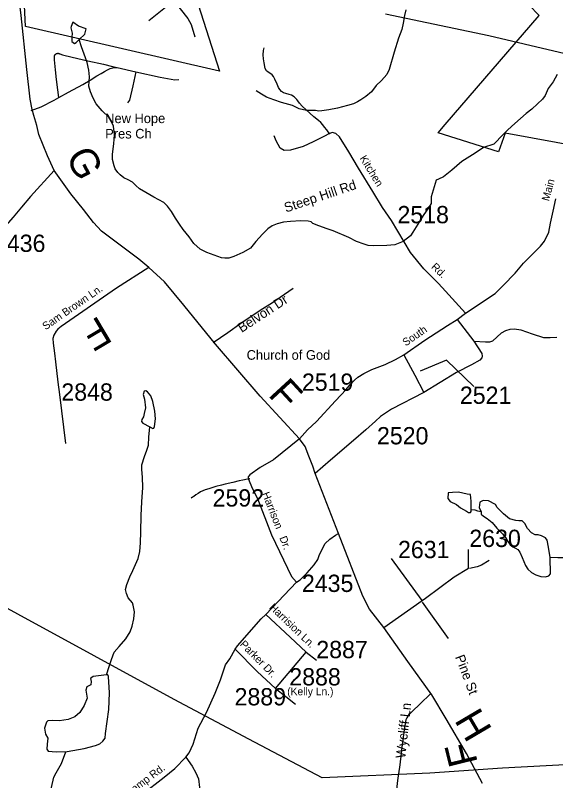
# Model space of a CAD drawing. Extents: x 1268485 to 1426702, y 514839 to 616766.
# Drawn here: x 1377903 to 1382514, y 533756 to 540290 of the extents above; entities that cross this region are included whole.
import ezdxf

# ---------------------------------------------------------------- set-up
doc = ezdxf.new("R2010")
doc.units = 0
for name, color, linetype in [('Old_Level_10', 7, 'Continuous'), ('Old_Level_11', 7, 'Continuous'), ('Old_Level_22', 7, 'Continuous'), ('Old_Level_29', 7, 'Continuous'), ('Old_Level_32', 7, 'Continuous'), ('Old_Level_35', 7, 'Continuous'), ('Old_Level_48', 7, 'Continuous'), ('Old_Level_49', 7, 'Continuous'), ('Old_Level_56', 7, 'Continuous'), ('Old_Level_62', 7, 'Continuous'), ('Old_Level_8', 7, 'Continuous')]:
    doc.layers.add(name, color=color, linetype=linetype)

msp = doc.modelspace()

# ---------------------------------------------------------------- linework, layer by layer
at = {"layer": 'Old_Level_11'}
msp.add_lwpolyline([(1381816.1, 537121.031), (1381582.771, 537345.868), (1381358.085, 537250.745)], dxfattribs=at)
at = {"layer": 'Old_Level_22'}
msp.add_line((1378670.085, 539451.621), (1378670.085, 539451.621), dxfattribs=at)
at = {"layer": 'Old_Level_29'}
msp.add_line((1380661.798, 535865.812), (1380461.639, 536377.474), dxfattribs=at)
for points in [[(1378235.034, 538965.895), (1378176.071, 539089.297), (1378102.134, 539273.422), (1378086.167, 539347.983), (1378059.556, 539433.197), (1378047.317, 539485.38), (1378028.688, 539573.256), (1378002.076, 539826.232), (1377953.11, 540287.991), (1377902.548, 540705.537), (1377889.243, 540875.964), (1377870.614, 541040.532), (1377838.68, 541160.363), (1377796.102, 541258.891), (1377745.541, 541328.126), (1377734.896, 541352.093), (1377657.723, 541437.306), (1377290.855, 541774.023), (1377172.929, 541894.415), (1377036.385, 542002.767)], [(1379043.439, 538138.202), (1378956.548, 538207.427), (1378832.888, 538301.982), (1378638.46, 538448.211), (1378570.188, 538520.446), (1378484.277, 538632.183), (1378377.785, 538767.249), (1378235.034, 538965.895)], [(1380328.199, 536675.443), (1379993.044, 537039.628), (1379609.789, 537482.067), (1379341.354, 537816.154), (1379176.88, 538014.8), (1379043.439, 538138.202)], [(1380461.639, 536377.474), (1380441.468, 536440.679), (1380408.86, 536525.906), (1380376.299, 536609.227), (1380328.199, 536675.443)], [(1381047.378, 535063.728), (1380925.576, 535220.991), (1380868.165, 535332.354), (1380661.798, 535865.812)], [(1381889.32, 533731.881), (1381754.307, 533989.571), (1381580.368, 534284.94), (1381457.788, 534488.101), (1381251.351, 534773.539), (1381047.378, 535063.728)]]:
    msp.add_lwpolyline(points, dxfattribs=at)
at = {"layer": 'Old_Level_32'}
for p, q in [((1381672.694, 537694.257), (1381744.069, 537748.434)), ((1381672.694, 537694.257), (1381816.221, 537507.648)), ((1381374, 535293.225), (1381112.548, 535652.145)), ((1380041.048, 535175.725), (1380302.593, 535451.964)), ((1381047.378, 535063.728), (1381374, 535293.225)), ((1380124.155, 534543.006), (1380383.809, 534852.45)), ((1380383.809, 534852.45), (1380472.498, 534785.296))]:
    msp.add_line(p, q, dxfattribs=at)
for points in [[(1380606.717, 539289.444), (1380572.581, 539275.9), (1380546.203, 539262.356), (1380445.346, 539209.684), (1380358.455, 539169.052), (1380250.751, 539139.737), (1380197.529, 539137.074), (1380162.934, 539155.714), (1380128.338, 539216.962), (1380112.372, 539262.231)], [(1381744.069, 537748.434), (1381573.881, 537934.445), (1381515.336, 538001.018), (1381387.601, 538124.578), (1381275.833, 538265.714), (1381112.922, 538538.279), (1381037.299, 538648.361), (1380953.51, 538786.811), (1380830.016, 538986.38), (1380749.468, 539125.411), (1380668.783, 539251.822), (1380637.749, 539281.92), (1380606.717, 539289.444)], [(1378235.034, 538965.895), (1378031.882, 538744.026), (1377954.708, 538650.824), (1377885.519, 538565.611), (1377656.128, 538309.97), (1377420.88, 538059.134), (1377223.955, 537846.1), (1377202.666, 537811.482), (1377108.533, 537607.766), (1377086.81, 537499.414), (1377058.881, 537087.07), (1377056.303, 536596.66), (1377050.981, 536442.212), (1376998.366, 536149.516), (1376973.54, 536026.113), (1376874.235, 535640.859), (1376787.343, 535300.751), (1376751.286, 535157.206), (1376653.902, 534769.521), (1376618.214, 534698.79), (1376575.545, 534625.801), (1376519.685, 534541.527), (1376487.101, 534485.846)], [(1381744.069, 537748.434), (1381996.987, 537913.971), (1382066.193, 537982.378), (1382167.317, 538088.895), (1382238.265, 538174.32), (1382385.671, 538318.79), (1382417.479, 538362.433), (1382454.718, 538437.678), (1382470.235, 538514.428), (1382493.509, 538618.265), (1382514.456, 538722.103)], [(1379043.439, 538138.202), (1378767.239, 537961.416), (1378292.766, 537632.396), (1378264.321, 537610.959), (1378250.542, 537592.716), (1378230.371, 537559.609), (1378224.164, 537529.51), (1378225.715, 537490.383), (1378236.577, 537404.603), (1378244.336, 537330.863), (1378266.835, 537158.551), (1378279.248, 537051.703), (1378331.228, 536634.092)], [(1381218.838, 537392.167), (1381398.246, 537515.564), (1381590.457, 537641.586), (1381672.694, 537694.257)], [(1381816.221, 537507.648), (1381913.974, 537501.629), (1381951.213, 537501.629), (1381977.591, 537510.658), (1382013.279, 537542.261), (1382052.07, 537578.378), (1382087.758, 537599.447), (1382126.549, 537611.486), (1382163.788, 537612.991), (1382216.544, 537603.961), (1382314.297, 537569.349), (1382409.723, 537539.251), (1382468.258, 537540.469), (1382524.147, 537543.132)], [(1381816.221, 537507.648), (1381882.941, 537403.813), (1381887.596, 537379.734), (1381884.493, 537366.19), (1381865.873, 537345.122), (1381796.05, 537307.5), (1381667.263, 537239.779), (1381388.745, 537071.232)], [(1380328.199, 536675.443), (1380394.919, 536750.688), (1380472.501, 536822.923), (1380633.871, 536997.491), (1380726.97, 537096.814), (1380767.313, 537144.97), (1380798.345, 537175.069), (1380826.275, 537202.157), (1380876.661, 537231.429), (1380944.2, 537265.362), (1381058.246, 537309.005), (1381148.24, 537351.143), (1381218.838, 537392.167)], [(1381218.838, 537392.167), (1381311.163, 537218.712), (1381388.745, 537071.232)], [(1381388.745, 537071.232), (1381113.503, 536928.654), (1381020.363, 536864.743), (1380975.123, 536824.799), (1380892.628, 536750.237), (1380788.843, 536659.697), (1380593.529, 536493.35), (1380461.639, 536377.474)], [(1380328.199, 536675.443), (1380104.915, 536494.397), (1379991.492, 536428.64), (1379904.802, 536366.581), (1379888.836, 536350.603), (1379892.187, 536329.317), (1379922.953, 536253.755), (1379968.217, 536163.779), (1380088.622, 535856.236), (1380259.147, 535498.616), (1380302.593, 535451.964)], [(1380302.593, 535451.964), (1380333.626, 535471.528), (1380392.588, 535531.724), (1380453.1, 535599.474), (1380484.133, 535644.621), (1380497.324, 535686.729), (1380546.976, 535780.033), (1380585.765, 535818.438), (1380633.867, 535853.05), (1380661.798, 535865.812)], [(1381374, 535293.225), (1381404.256, 535313.542), (1381647.865, 535495.635), (1381768.895, 535570.881), (1381769.517, 535730.481)], [(1379780.255, 534877.478), (1379798.31, 534907.191), (1380001.13, 535138.444), (1380041.048, 535175.725)], [(1380041.048, 535175.725), (1380248.091, 534982.401), (1380383.809, 534852.45)], [(1379357.644, 533956.097), (1379385.573, 533995.225), (1379421.262, 534067.46), (1379462.379, 534204.405), (1379535.43, 534339.57), (1379607.281, 534502.008), (1379652.52, 534616.513), (1379697.759, 534744.333), (1379732.354, 534797.591), (1379780.255, 534877.478)], [(1379780.255, 534877.478), (1379967.439, 534687.477), (1380124.155, 534543.006)], [(1380124.155, 534543.006), (1380211.823, 534475.287), (1380294.059, 534410.576)], [(1378230.88, 532361.466), (1378262.2, 532445.754), (1378378.559, 532747.667), (1378510.449, 533125.395), (1378547.688, 533241.272), (1378570.963, 533295.449), (1378606.65, 533333.071), (1378698.197, 533421.86), (1378869.654, 533552.787), (1378981.372, 533637.061), (1379172.224, 533786.046), (1379263.771, 533859.785), (1379357.644, 533956.097)], [(1379357.644, 533956.097), (1379411.951, 533880.853), (1379442.985, 533822.162), (1379464.707, 533772.5), (1379474.017, 533697.255), (1379467.811, 533632.545), (1379449.967, 533581.378), (1379437.554, 533537.736)]]:
    msp.add_lwpolyline(points, dxfattribs=at)
at = {"layer": 'Old_Level_35'}
for p, q in [((1379254.542, 540414.048), (1379041.083, 540243.445)), ((1378771.747, 539843.338), (1378930.047, 539808.017)), ((1381373.345, 535279.852), (1381597.262, 534970.428))]:
    msp.add_line(p, q, dxfattribs=at)
for points in [[(1379254.542, 540414.048), (1379374.702, 540262.823), (1379403.717, 540212.38), (1379434.783, 540105.753)], [(1378236.458, 539932.996), (1378236.458, 539933.663), (1378236.356, 539934.381), (1378236.356, 539935.047), (1378236.356, 539935.714), (1378236.356, 539936.38), (1378236.356, 539937.046), (1378236.356, 539937.764), (1378236.458, 539938.43), (1378236.458, 539939.148), (1378236.663, 539939.815), (1378236.766, 539940.481), (1378236.868, 539941.147), (1378236.971, 539941.813), (1378237.176, 539942.48), (1378237.278, 539943.146), (1378237.381, 539943.813), (1378237.586, 539944.428), (1378237.894, 539945.146), (1378237.996, 539945.761), (1378238.201, 539946.376), (1378238.509, 539947.042), (1378238.714, 539947.709), (1378239.021, 539948.324), (1378239.329, 539948.939), (1378239.637, 539949.503), (1378240.047, 539950.118), (1378240.252, 539950.682), (1378240.662, 539951.298), (1378240.969, 539951.861), (1378241.38, 539952.425), (1378241.79, 539952.989), (1378242.097, 539953.553), (1378242.61, 539954.117), (1378243.02, 539954.629), (1378243.328, 539955.194), (1378243.84, 539955.706), (1378244.353, 539956.167), (1378244.763, 539956.68), (1378245.275, 539957.192), (1378245.788, 539957.603), (1378246.301, 539958.064), (1378246.711, 539958.577), (1378247.326, 539958.987), (1378247.839, 539959.397), (1378248.351, 539959.807), (1378248.966, 539960.166), (1378249.479, 539960.576), (1378250.094, 539960.935), (1378250.607, 539961.293), (1378251.222, 539961.704), (1378251.837, 539962.011), (1378252.452, 539962.319), (1378253.17, 539962.626), (1378253.785, 539962.934), (1378254.4, 539963.191), (1378255.015, 539963.446), (1378255.631, 539963.703), (1378256.246, 539963.959), (1378256.861, 539964.113), (1378257.476, 539964.318), (1378258.091, 539964.523), (1378258.911, 539964.677), (1378259.527, 539964.882), (1378260.142, 539964.984), (1378260.859, 539965.139), (1378261.475, 539965.241), (1378262.295, 539965.292), (1378262.91, 539965.394), (1378263.525, 539965.446), (1378264.243, 539965.497), (1378264.858, 539965.549), (1378265.576, 539965.549), (1378266.293, 539965.549), (1378267.011, 539965.549), (1378267.626, 539965.497), (1378268.344, 539965.446), (1378268.959, 539965.394), (1378269.677, 539965.292), (1378270.394, 539965.241), (1378271.01, 539965.139), (1378271.727, 539964.984), (1378272.342, 539964.882), (1378272.958, 539964.677), (1378273.675, 539964.523), (1378274.393, 539964.318), (1378275.008, 539964.113), (1378275.623, 539963.959), (1378276.238, 539963.703), (1378276.854, 539963.446), (1378277.469, 539963.191), (1378278.084, 539962.934), (1378278.802, 539962.626), (1378279.417, 539962.319), (1378280.032, 539962.011), (1378280.647, 539961.704), (1378281.16, 539961.293), (1378281.775, 539960.935), (1378282.39, 539960.576), (1378282.903, 539960.166)], [(1378282.903, 539960.166), (1378304.125, 539951.143), (1378387.787, 539932.996), (1378522.711, 539901.726), (1378655.79, 539871.481), (1378733.402, 539853.385), (1378771.747, 539843.338)], [(1380586.253, 539276.061), (1380560.519, 539312.048), (1380541.961, 539335.269), (1380526.275, 539355.365), (1380509.05, 539375.101), (1380490.596, 539390.993), (1380450.713, 539424.416), (1380352.083, 539514.485), (1380328.707, 539540.322), (1380313.328, 539560.827), (1380305.126, 539572.054), (1380281.033, 539594.199), (1380260.22, 539607.323), (1380240.022, 539613.679), (1380210.29, 539621.676), (1380191.63, 539627.828), (1380173.483, 539639.259), (1380159.642, 539655.663), (1380150.004, 539672.58), (1380136.266, 539701.185), (1380118.016, 539744.451), (1380106.738, 539767.519), (1380095.153, 539781.77), (1380074.853, 539795.509), (1380059.166, 539804.634), (1380047.376, 539817.039), (1380034.355, 539835.751), (1380025.333, 539885.066), (1380020.206, 539918.079), (1380017.336, 539952.066), (1380020.206, 539988.565), (1380027.588, 540011.941)], [(1378272.855, 539587.33), (1378264.755, 539652.793), (1378254.605, 539740.504), (1378244.66, 539824.114), (1378236.458, 539908.8), (1378236.458, 539932.996)], [(1378272.855, 539587.33), (1378356.516, 539632.647), (1378478.42, 539699.186), (1378540.858, 539735.429), (1378598.375, 539771.774), (1378634.669, 539791.87), (1378663.889, 539808.991), (1378688.085, 539824.114), (1378712.282, 539835.238), (1378735.35, 539842.312), (1378752.574, 539844.311), (1378771.747, 539843.338)], [(1378930.047, 539808.017), (1378904.723, 539688.062), (1378876.528, 539566.107), (1378861.354, 539541.962)], [(1378930.047, 539808.017), (1379139.61, 539762.7), (1379264.589, 539738.504), (1379297.91, 539740.504)], [(1378038.378, 539476.499), (1378122.654, 539509.666), (1378235.536, 539566.107), (1378272.855, 539587.33)], [(1379590.725, 537497.49), (1379716.729, 537581.869), (1379828.483, 537661.994), (1379999.906, 537777.694), (1380089.719, 537832.289), (1380272.728, 537961.113)], [(1379904.762, 536332.487), (1379882.924, 536328.95), (1379845.707, 536322.439), (1379812.796, 536314.75), (1379758.355, 536302.396), (1379694.584, 536287.017), (1379662.801, 536279.943), (1379613.793, 536266.922), (1379587.239, 536259.898), (1379553.508, 536248.62), (1379523.468, 536238.625), (1379502.757, 536230.935), (1379484.508, 536222.066), (1379462.67, 536208.482), (1379441.959, 536194.948), (1379424.838, 536182.543), (1379414.277, 536175.417), (1379404.537, 536167.42)], [(1381947.286, 535634.541), (1381881.464, 535596.606), (1381843.222, 535582.048), (1381777.708, 535567.797)], [(1381446.036, 534496.605), (1381357.453, 534410.893), (1381289.479, 534345.994), (1381271.332, 534331.025), (1381259.541, 534320.106), (1381251.339, 534307.854), (1381244.162, 534293.398), (1381235.55, 534274.328), (1381224.58, 534209.89), (1381204.075, 534065.585), (1381183.774, 533892.675), (1381165.627, 533756.982), (1381147.48, 533602.68), (1381140.201, 533553.262), (1381132.511, 533526.913), (1381123.489, 533513.175), (1381110.878, 533495.181), (1381091.398, 533472.677), (1381072.636, 533444.79), (1381056.232, 533420.747), (1381045.467, 533409.674), (1381029.78, 533401.421), (1381000.355, 533393.937)]]:
    msp.add_lwpolyline(points, dxfattribs=at)
at = {"layer": 'Old_Level_48'}
for points in [[(1379461.962, 540383.078), (1379644.124, 539813.886), (1377990.859, 540195.19), (1377979.819, 540374.789)], [(1382752.667, 539161.552), (1382084.001, 539283.376), (1382027.535, 539123.549), (1381510.576, 539286.426), (1381570.067, 539359.063), (1382371.931, 540286.961), (1382283.739, 540378.779)]]:
    msp.add_lwpolyline(points, dxfattribs=at)
at = {"layer": 'Old_Level_49'}
for points in [[(1379461.962, 540383.078), (1379644.124, 539813.886), (1377990.859, 540195.19), (1377979.819, 540374.789)], [(1382752.667, 539161.552), (1382084.001, 539283.376), (1382027.535, 539123.549), (1381510.576, 539286.426), (1381570.067, 539359.063), (1382371.931, 540286.961), (1382283.739, 540378.779)]]:
    msp.add_lwpolyline(points, dxfattribs=at)
at = {"layer": 'Old_Level_56'}
for points in [[(1381061.503, 540301.744), (1381944.122, 540117.691), (1382895.855, 539893.836), (1383489.307, 539753.631), (1384243.94, 539479.72), (1384403.305, 539444.497), (1385295.195, 539229.852), (1386225.65, 539032.439)], [(1386319.571, 534122.074), (1385381.998, 534065.509), (1384514.51, 534011.536), (1383073.945, 533917.273), (1382060.172, 533862.442), (1381439.057, 533821.319), (1380521.804, 533780.153), (1379894.345, 534109.329), (1379257.086, 534448.709), (1377238.959, 535551.224), (1376368.712, 536035.56), (1375939.406, 536278.51), (1373794.637, 537441.607), (1372983.341, 537882.537), (1372761.263, 538001.427), (1371303.275, 538781.963), (1370885.605, 538996.668), (1370094.313, 539437.396), (1369288.815, 539868.206), (1368639.834, 540221.831)]]:
    msp.add_lwpolyline(points, dxfattribs=at)
at = {"layer": 'Old_Level_62'}
for points in [[(1381236.37, 540336.898), (1381223.247, 540288.762), (1381211.867, 540223.299), (1381200.691, 540167.73), (1381173.214, 540093.604), (1381136.817, 539976.211), (1381093.654, 539827.702), (1381072.841, 539785.461), (1381027.73, 539734.66), (1380982.823, 539689.599), (1380941.608, 539636.286), (1380894.753, 539597.839), (1380852.103, 539568.311), (1380821.857, 539550.882), (1380787.409, 539533.555), (1380737.068, 539518.945), (1380652.587, 539496.03), (1380578.256, 539483.574), (1380518.073, 539473.321), (1380493.979, 539471.321), (1380464.042, 539476.038), (1380388.07, 539477.576), (1380324.401, 539491.161), (1380266.884, 539518.586), (1380173.278, 539544.269), (1380107.866, 539567.748), (1380046.248, 539591.124), (1380004.827, 539615.73), (1379959.306, 539644.59)], [(1378447.662, 540082.838), (1378496.772, 540129.436), (1378506.852, 540175.356), (1378442.689, 540196.758), (1378392.783, 540232.428), (1378379.995, 540194.182), (1378377.739, 540181.879), (1378386.864, 540137.382), (1378386.146, 540102.113), (1378385.326, 540067.665), (1378397.117, 540057.617), (1378408.907, 540049.158), (1378423.158, 540058.693), (1378447.662, 540082.838)], [(1378700.081, 539421.289), (1378645.23, 539475.73), (1378592.326, 539533.401), (1378567.412, 539583.947), (1378544.446, 539636.133), (1378531.426, 539684.781), (1378532.246, 539724.151), (1378535.117, 539764.341), (1378530.298, 539822.678), (1378515.637, 539886.962), (1378489.185, 539957.295), (1378468.372, 540020.041), (1378447.662, 540082.838)], [(1382525.43, 539783.308), (1382492.212, 539722.408), (1382448.946, 539665.045), (1382425.775, 539605.58), (1382400.964, 539574.104), (1382360.158, 539534.683), (1382309.203, 539489.776), (1382262.451, 539451.329), (1382164.641, 539367.155), (1382105.483, 539312.509), (1382064.678, 539273.139), (1381985.023, 539190.287), (1381899.471, 539161.749), (1381828.178, 539111.809), (1381714.109, 539040.466), (1381628.558, 538969.124), (1381557.264, 538912.048), (1381514.489, 538890.646), (1381493.101, 538883.512), (1381450.325, 538740.825), (1381450.325, 538683.751), (1381427.376, 538647.525), (1381381.957, 538581.14), (1381338.384, 538507.372), (1381294.913, 538438.474), (1381274.305, 538406.896), (1381213.199, 538358.043), (1381142.559, 538331.591), (1381074.482, 538324.773), (1380958.32, 538321.339), (1380914.336, 538324.67), (1380878.554, 538335.23), (1380813.143, 538360.349), (1380749.679, 538392.03), (1380614.755, 538450.521), (1380565.235, 538467.951), (1380493.672, 538493.172), (1380442.101, 538512.242), (1380426.312, 538526.544), (1380400.475, 538532.798), (1380338.447, 538536.489), (1380252.325, 538530.03), (1380190.195, 538523.878), (1380137.906, 538511.012), (1380093.41, 538491.378), (1380056.911, 538468.309), (1380011.902, 538420.789), (1379956.538, 538357.94), (1379909.376, 538303.089), (1379844.579, 538264.18), (1379767.992, 538232.038), (1379723.598, 538217.377), (1379691.508, 538215.532), (1379661.57, 538218.607), (1379536.488, 538264.59), (1379481.124, 538294.477), (1379426.068, 538341.536), (1379385.16, 538398.131), (1379334.512, 538461.543), (1379303.447, 538508.089), (1379268.485, 538558.84), (1379235.575, 538613.691), (1379202.459, 538660.29), (1379169.138, 538692.995), (1379127.615, 538715.961), (1379086.092, 538738.158), (1379016.784, 538778.092), (1378961.522, 538808.747), (1378931.995, 538835.609), (1378902.672, 538864.111), (1378867.096, 538885.334), (1378829.366, 538901.687), (1378797.891, 538928.6), (1378778.308, 538948.644), (1378754.932, 538977.864), (1378745.5, 539003.495), (1378732.684, 539060.346), (1378731.454, 539103.868), (1378743.347, 539193.938), (1378748.986, 539271.755), (1378740.476, 539344.138), (1378719.356, 539384.79), (1378700.081, 539421.289)], [(1379051.233, 536775.964), (1379077.069, 536761.507), (1379085.066, 536765.403), (1379089.372, 536779.295), (1379098.805, 536845.579), (1379092.141, 536911.349), (1379075.839, 536993.729), (1379058.922, 537042.48), (1379031.548, 537076.672), (1379015.656, 537082.772), (1379001.61, 537081.389), (1378995.151, 537053.655), (1379004.276, 537013.26), (1379012.683, 536939.236), (1379003.661, 536890.998), (1378997.099, 536861.573), (1378982.54, 536838.043), (1378980.182, 536821.69), (1378990.025, 536809.182), (1379051.233, 536775.964)], [(1378679.739, 534660.285), (1378702.644, 534732.26), (1378723.97, 534790.137), (1378747.243, 534852.011), (1378790.304, 534900.403), (1378845.668, 534965.712), (1378882.885, 535026.51), (1378899.904, 535074.595), (1378915.283, 535136.675), (1378920.409, 535196.447), (1378907.696, 535254.169), (1378902.057, 535274.777), (1378866.891, 535317.326), (1378851.717, 535355.414), (1378844.438, 535387.556), (1378853.255, 535430.053), (1378880.629, 535495.157), (1378905.851, 535550.418), (1378951.885, 535652.073), (1378965.213, 535711.743), (1378970.647, 535785.459), (1378974.646, 535881.372), (1378977.516, 536019.219), (1378982.028, 536137.277), (1378990.64, 536259.386), (1378988.384, 536347.2), (1378981.618, 536411.381), (1378982.643, 536453.212), (1379004.071, 536523.339), (1379025.191, 536577.063), (1379038.109, 536620.329), (1379043.543, 536688.304), (1379051.233, 536775.964)], [(1381794.009, 536069.2), (1381793.394, 536143.07), (1381786.063, 536198.516), (1381757.546, 536201.37), (1381683.401, 536218.492), (1381634.922, 536215.638), (1381597.85, 536212.785), (1381593.879, 536165.113), (1381613.358, 536138.457), (1381668.825, 536113.543), (1381702.249, 536084.989), (1381751.666, 536056.077), (1381769.403, 536045.876), (1381787.448, 536045.516), (1381791.651, 536052.847), (1381794.009, 536069.2)], [(1382467.811, 535660.941), (1382453.365, 535750.482), (1382441.958, 535810.409), (1382427.7, 535830.386), (1382393.479, 535847.508), (1382364.962, 535856.069), (1382339.296, 535856.069), (1382307.927, 535873.191), (1382273.707, 535910.29), (1382250.893, 535950.242), (1382228.079, 535973.071), (1382199.562, 535973.071), (1382173.897, 535975.926), (1382119.714, 535990.194), (1382068.383, 536033), (1382014.201, 536087.221), (1381999.942, 536112.905), (1381940.056, 536144.295), (1381894.428, 536147.149), (1381865.911, 536132.88), (1381860.208, 536087.221), (1381877.671, 536051.104)], [(1381877.671, 536051.104), (1381849.681, 536055.769), (1381827.945, 536066.073), (1381794.009, 536069.2)], [(1381877.671, 536051.104), (1381879.209, 536031.368), (1381896.946, 536014.605), (1381928.524, 535994.253), (1381971.79, 535961.394), (1382010.749, 535910.541), (1382059.859, 535863.635), (1382087.234, 535832.724), (1382106.406, 535798.685), (1382125.886, 535770.388), (1382147.519, 535751.882), (1382171.305, 535740.758), (1382191.093, 535728.865), (1382208.625, 535706.36), (1382227.695, 535660.018), (1382256.299, 535592.966), (1382277.727, 535562.978), (1382307.05, 535534.527), (1382344.677, 535513.253), (1382386.405, 535498.437), (1382428.441, 535497.617), (1382456.533, 535505.256), (1382468.836, 535520.583), (1382467.811, 535660.941)], [(1383441.44, 536026.793), (1383354.495, 535906.32), (1383296.016, 535846.103), (1383225.478, 535822.932), (1383153.197, 535810.424), (1383048.928, 535794.482), (1382994.794, 535793.917), (1382952.759, 535794.789), (1382924.769, 535793.712), (1382898.625, 535784.383), (1382868.38, 535774.335), (1382847.875, 535750.908), (1382829.522, 535735.683), (1382799.072, 535715.793), (1382718.384, 535683.754), (1382676.143, 535672.322), (1382619.959, 535663.607), (1382575.77, 535658.737), (1382531.787, 535659.66), (1382467.811, 535660.941)], [(1378251.79, 534001.95), (1378345.909, 534004.154), (1378490.573, 534031.58), (1378587.255, 534057.57), (1378623.446, 534070.796), (1378650.001, 534094.018), (1378670.506, 534119.906), (1378673.377, 534159.225), (1378699.701, 534363.511), (1378705.405, 534506.191), (1378697.47, 534645.352), (1378691.729, 534659.398), (1378679.739, 534660.285)], [(1378679.739, 534660.285), (1378568.522, 534646.018), (1378545.709, 534628.896), (1378551.413, 534603.214), (1378548.561, 534574.678), (1378514.34, 534557.556)], [(1378514.34, 534557.556), (1378505.784, 534529.02), (1378516.923, 534461.71), (1378491.599, 534398.195), (1378452.434, 534338.269), (1378409.578, 534301.411), (1378355.034, 534278.701), (1378280.805, 534267.885), (1378218.777, 534269.115), (1378180.74, 534266.603), (1378168.539, 534256.197), (1378152.172, 534203.71), (1378160.727, 534152.345), (1378179.612, 534118.094), (1378174.985, 534066.737), (1378172.133, 534023.933), (1378183.541, 534006.812), (1378251.79, 534001.95)], [(1378193.214, 532405.275), (1378189.194, 532650.059), (1378191.962, 532782.112), (1378156.283, 533088.922), (1378150.952, 533121.064), (1378155.668, 533155.41), (1378174.533, 533194.421), (1378185.298, 533232.766), (1378188.374, 533280.286), (1378181.607, 533340.367), (1378184.99, 533406.753), (1378182.115, 533444.654), (1378174.985, 533484.604), (1378180.689, 533547.383), (1378206.354, 533635.844), (1378212.058, 533698.623), (1378232.02, 533787.085), (1378251.632, 533823.111), (1378297.61, 533904.083), (1378334.286, 534001.95)]]:
    msp.add_lwpolyline(points, dxfattribs=at)

# ---------------------------------------------------------------- texts
at = {"layer": 'Old_Level_10'}
for s, height, rotation, p in [('Steep Hill Rd', 82.02083, 18.5807, (1380212.89, 538605.759)), ('Belvon Dr', 82.0208, 33.3121083, (1379834.924, 537578.076)), ('Pine St', 82.0208, 290.7100722, (1381654.848, 534812.917)), ('Wycliff Ln', 82.0208, 83.7695556, (1381229.888, 533943.623))]:
    msp.add_text(s, height=height, rotation=rotation, dxfattribs=at).set_placement(p)
at = {"layer": 'Old_Level_11'}
for s, height, rotation, p in [('Kitchen', 65.6167, 301.7493389, (1380838.142, 539069.326)), ('Main', 65.6167, 74.8641167, (1382455.948, 538699.401)), ('Rd.', 65.6167, 315.9519778, (1381446.811, 538136.446)), ('Sam Brown Ln.', 65.61666, 34.7390222, (1378162.029, 537600.508)), ('South', 65.6167, 34.5203278, (1381234.786, 537462.43)), ('Harrison   Dr.', 65.61666, 291.3805194, (1380007.308, 536206.523)), ('Harrision Ln.', 65.61666, 316.2437028, (1380064.36, 535229.345)), ('Parker Dr.', 65.6167, 314.5720333, (1379814.516, 534915.18)), ('Stowe Fish Camp Rd.', 65.61666, 37.028875, (1378506.106, 533338.807))]:
    msp.add_text(s, height=height, rotation=rotation, dxfattribs=at).set_placement(p)
msp.add_text('(Kelly Ln.)', height=65.61666, dxfattribs=at).set_placement((1380223.032, 534485.405))
at = {"layer": 'Old_Level_22'}
for s, height, p in [('New Hope', 82.0208, (1378670.085, 539369.6)), ('Pres Ch', 82.0208, (1378670.085, 539238.367)), ('Church of God', 82.02083, (1379876.799, 537349.354))]:
    msp.add_text(s, height=height, dxfattribs=at).set_placement(p)
for s, rotation, p in [('G', 297.6368111, (1378328.145, 539086.103)), ('F', 210.763125, (1378619.398, 537729.142)), ('F', 312.6229444, (1380053.265, 537047.116)), ('H', 300.4932722, (1381644.922, 534272.684)), ('F', 103.8304583, (1381850.369, 533910.375))]:
    msp.add_text(s, height=246.062, rotation=rotation, dxfattribs=at).set_placement(p)
at = {"layer": 'Old_Level_8'}
for s, p in [('2518', (1381163.956, 538514.524)), ('2436', (1377720.702, 538269.977)), ('2519', (1380348.435, 537084.523)), ('2848', (1378295.69, 537000.122)), ('2521', (1381696.431, 536973.087)), ('2520', (1380989.1, 536627.048)), ('2592', (1379586.575, 536096.37)), ('2630', (1381777.374, 535751.043)), ('2631', (1381168.658, 535655.745)), ('2435', (1380348.581, 535367.18)), ('2887', (1380471.319, 534801.93)), ('2888', (1380240.942, 534569.095)), ('2889', (1379773.958, 534398.863))]:
    msp.add_text(s, height=147.6375, dxfattribs=at).set_placement(p)

doc.saveas('drawing.dxf')
